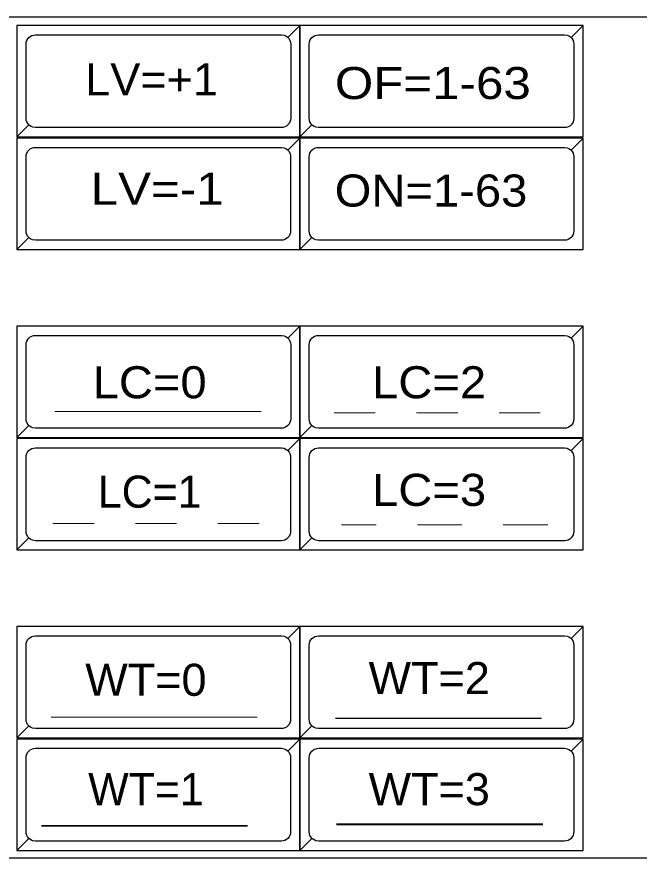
# Model space of a CAD drawing. Extents: x 16898 to 16911.6, y 15837.8 to 15842.
# Drawn here: x 16899.217 to 16900.726, y 15839.972 to 15842.012 of the extents above; entities that cross this region are included whole.
import ezdxf
from ezdxf.enums import TextEntityAlignment as Align

# ---------------------------------------------------------------- set-up
doc = ezdxf.new("R2010")
doc.units = 0
doc.header["$LTSCALE"] = 0.018
for name, pattern in [('DOTTED', [1.5, 0.3, -1.2]), ('LONG_DASHED', [7.5, 6, -1.5]), ('MEDIUM_DASHED', [4.5, 3, -1.5])]:
    doc.linetypes.add(name, pattern=pattern)
for name, color, linetype, lineweight in [('1', 7, 'Continuous', 25), ('2', 7, 'Continuous', 13), ('5', 7, 'Continuous', 13)]:
    doc.layers.add(name, color=color, linetype=linetype, lineweight=lineweight)

msp = doc.modelspace()

# ---------------------------------------------------------------- linework, layer by layer
at = {"layer": '1'}
for points in [[(16897.9955, 15839.9723), (16897.9955, 15842.0124), (16911.4764, 15842.0124), (16911.5674, 15841.9251), (16911.5674, 15840.0599), (16911.4764, 15839.9723)], [(16899.2172, 15841.7212), (16899.9036, 15841.7212), (16899.9036, 15841.9912), (16899.2172, 15841.9912)], [(16899.2172, 15841.7212), (16899.9036, 15841.7212), (16899.9036, 15841.9912), (16899.8745, 15841.9621), (16899.8773, 15841.9587), (16899.8794, 15841.9548), (16899.8806, 15841.9506), (16899.8811, 15841.9462), (16899.8811, 15841.7662), (16899.8806, 15841.7618), (16899.8794, 15841.7576), (16899.8773, 15841.7537), (16899.8745, 15841.7503), (16899.8745, 15841.7503), (16899.8711, 15841.7475), (16899.8672, 15841.7454), (16899.863, 15841.7441), (16899.8586, 15841.7437), (16899.2622, 15841.7437), (16899.2556, 15841.7447), (16899.2516, 15841.7464), (16899.2479, 15841.7488), (16899.2463, 15841.7503)], [(16899.9036, 15841.9912), (16899.2172, 15841.9912), (16899.2172, 15841.7212), (16899.2463, 15841.7503), (16899.2435, 15841.7537), (16899.2414, 15841.7576), (16899.2401, 15841.7618), (16899.2397, 15841.7662), (16899.2397, 15841.9462), (16899.2401, 15841.9506), (16899.2414, 15841.9548), (16899.2435, 15841.9587), (16899.2463, 15841.9621), (16899.2463, 15841.9621), (16899.2497, 15841.9649), (16899.2536, 15841.967), (16899.2578, 15841.9682), (16899.2622, 15841.9687), (16899.8586, 15841.9687), (16899.8652, 15841.9677), (16899.8692, 15841.966), (16899.8729, 15841.9636), (16899.8745, 15841.9621)], [(16899.9036, 15841.7212), (16900.59, 15841.7212), (16900.59, 15841.9912), (16899.9036, 15841.9912)], [(16899.9036, 15841.7212), (16900.59, 15841.7212), (16900.59, 15841.9912), (16900.5609, 15841.9621), (16900.5637, 15841.9587), (16900.5658, 15841.9548), (16900.567, 15841.9506), (16900.5675, 15841.9462), (16900.5675, 15841.7662), (16900.567, 15841.7618), (16900.5658, 15841.7576), (16900.5637, 15841.7537), (16900.5609, 15841.7503), (16900.5609, 15841.7503), (16900.5575, 15841.7475), (16900.5536, 15841.7454), (16900.5494, 15841.7441), (16900.545, 15841.7437), (16899.9486, 15841.7437), (16899.942, 15841.7447), (16899.938, 15841.7464), (16899.9343, 15841.7488), (16899.9327, 15841.7503)], [(16900.59, 15841.9912), (16899.9036, 15841.9912), (16899.9036, 15841.7212), (16899.9327, 15841.7503), (16899.9299, 15841.7537), (16899.9278, 15841.7576), (16899.9265, 15841.7618), (16899.9261, 15841.7662), (16899.9261, 15841.9462), (16899.9265, 15841.9506), (16899.9278, 15841.9548), (16899.9299, 15841.9587), (16899.9327, 15841.9621), (16899.9327, 15841.9621), (16899.9361, 15841.9649), (16899.94, 15841.967), (16899.9442, 15841.9682), (16899.9486, 15841.9687), (16900.545, 15841.9687), (16900.5516, 15841.9677), (16900.5556, 15841.966), (16900.5593, 15841.9636), (16900.5609, 15841.9621)], [(16899.2171, 15841.4483), (16899.9035, 15841.4483), (16899.9035, 15841.7183), (16899.2171, 15841.7183)], [(16899.2171, 15841.4483), (16899.9035, 15841.4483), (16899.9035, 15841.7183), (16899.8744, 15841.6892), (16899.8772, 15841.6858), (16899.8793, 15841.6819), (16899.8805, 15841.6777), (16899.881, 15841.6733), (16899.881, 15841.4933), (16899.8805, 15841.4889), (16899.8793, 15841.4847), (16899.8772, 15841.4808), (16899.8744, 15841.4774), (16899.8744, 15841.4774), (16899.871, 15841.4746), (16899.8671, 15841.4725), (16899.8629, 15841.4712), (16899.8585, 15841.4708), (16899.2621, 15841.4708), (16899.2555, 15841.4718), (16899.2515, 15841.4735), (16899.2478, 15841.4759), (16899.2462, 15841.4774)], [(16899.9035, 15841.7183), (16899.2171, 15841.7183), (16899.2171, 15841.4483), (16899.2462, 15841.4774), (16899.2434, 15841.4808), (16899.2413, 15841.4847), (16899.24, 15841.4889), (16899.2396, 15841.4933), (16899.2396, 15841.6733), (16899.24, 15841.6777), (16899.2413, 15841.6819), (16899.2434, 15841.6858), (16899.2462, 15841.6892), (16899.2462, 15841.6892), (16899.2496, 15841.692), (16899.2535, 15841.6941), (16899.2577, 15841.6953), (16899.2621, 15841.6958), (16899.8585, 15841.6958), (16899.8651, 15841.6948), (16899.8691, 15841.6931), (16899.8728, 15841.6907), (16899.8744, 15841.6892)], [(16899.9036, 15841.4483), (16900.59, 15841.4483), (16900.59, 15841.7183), (16899.9036, 15841.7183)], [(16899.9036, 15841.4483), (16900.59, 15841.4483), (16900.59, 15841.7183), (16900.5609, 15841.6892), (16900.5637, 15841.6858), (16900.5658, 15841.6819), (16900.567, 15841.6777), (16900.5675, 15841.6733), (16900.5675, 15841.4933), (16900.567, 15841.4889), (16900.5658, 15841.4847), (16900.5637, 15841.4808), (16900.5609, 15841.4774), (16900.5609, 15841.4774), (16900.5575, 15841.4746), (16900.5536, 15841.4725), (16900.5494, 15841.4712), (16900.545, 15841.4708), (16899.9486, 15841.4708), (16899.942, 15841.4718), (16899.938, 15841.4735), (16899.9343, 15841.4759), (16899.9327, 15841.4774)], [(16900.59, 15841.7183), (16899.9036, 15841.7183), (16899.9036, 15841.4483), (16899.9327, 15841.4774), (16899.9299, 15841.4808), (16899.9278, 15841.4847), (16899.9265, 15841.4889), (16899.9261, 15841.4933), (16899.9261, 15841.6733), (16899.9265, 15841.6777), (16899.9278, 15841.6819), (16899.9299, 15841.6858), (16899.9327, 15841.6892), (16899.9327, 15841.6892), (16899.9361, 15841.692), (16899.94, 15841.6941), (16899.9442, 15841.6953), (16899.9486, 15841.6958), (16900.545, 15841.6958), (16900.5516, 15841.6948), (16900.5556, 15841.6931), (16900.5593, 15841.6907), (16900.5609, 15841.6892)], [(16899.2172, 15840.9924), (16899.9036, 15840.9924), (16899.9036, 15841.2624), (16899.2172, 15841.2624)], [(16899.2172, 15840.9924), (16899.9036, 15840.9924), (16899.9036, 15841.2624), (16899.8745, 15841.2333), (16899.8773, 15841.2299), (16899.8794, 15841.226), (16899.8806, 15841.2218), (16899.8811, 15841.2174), (16899.8811, 15841.0374), (16899.8806, 15841.033), (16899.8794, 15841.0288), (16899.8773, 15841.0249), (16899.8745, 15841.0215), (16899.8745, 15841.0215), (16899.8711, 15841.0187), (16899.8672, 15841.0166), (16899.863, 15841.0153), (16899.8586, 15841.0149), (16899.2622, 15841.0149), (16899.2556, 15841.0159), (16899.2516, 15841.0176), (16899.2479, 15841.02), (16899.2463, 15841.0215)], [(16899.9036, 15841.2624), (16899.2172, 15841.2624), (16899.2172, 15840.9924), (16899.2463, 15841.0215), (16899.2435, 15841.0249), (16899.2414, 15841.0288), (16899.2401, 15841.033), (16899.2397, 15841.0374), (16899.2397, 15841.2174), (16899.2401, 15841.2218), (16899.2414, 15841.226), (16899.2435, 15841.2299), (16899.2463, 15841.2333), (16899.2463, 15841.2333), (16899.2497, 15841.2361), (16899.2536, 15841.2382), (16899.2578, 15841.2394), (16899.2622, 15841.2399), (16899.8586, 15841.2399), (16899.8652, 15841.2389), (16899.8692, 15841.2372), (16899.8729, 15841.2348), (16899.8745, 15841.2333)], [(16899.9036, 15840.9924), (16900.59, 15840.9924), (16900.59, 15841.2624), (16899.9036, 15841.2624)], [(16899.9036, 15840.9924), (16900.59, 15840.9924), (16900.59, 15841.2624), (16900.5609, 15841.2333), (16900.5637, 15841.2299), (16900.5658, 15841.226), (16900.567, 15841.2218), (16900.5675, 15841.2174), (16900.5675, 15841.0374), (16900.567, 15841.033), (16900.5658, 15841.0288), (16900.5637, 15841.0249), (16900.5609, 15841.0215), (16900.5609, 15841.0215), (16900.5575, 15841.0187), (16900.5536, 15841.0166), (16900.5494, 15841.0153), (16900.545, 15841.0149), (16899.9486, 15841.0149), (16899.942, 15841.0159), (16899.938, 15841.0176), (16899.9343, 15841.02), (16899.9327, 15841.0215)], [(16900.59, 15841.2624), (16899.9036, 15841.2624), (16899.9036, 15840.9924), (16899.9327, 15841.0215), (16899.9299, 15841.0249), (16899.9278, 15841.0288), (16899.9265, 15841.033), (16899.9261, 15841.0374), (16899.9261, 15841.2174), (16899.9265, 15841.2218), (16899.9278, 15841.226), (16899.9299, 15841.2299), (16899.9327, 15841.2333), (16899.9327, 15841.2333), (16899.9361, 15841.2361), (16899.94, 15841.2382), (16899.9442, 15841.2394), (16899.9486, 15841.2399), (16900.545, 15841.2399), (16900.5516, 15841.2389), (16900.5556, 15841.2372), (16900.5593, 15841.2348), (16900.5609, 15841.2333)], [(16899.2171, 15840.7196), (16899.9035, 15840.7196), (16899.9035, 15840.9896), (16899.2171, 15840.9896)], [(16899.2171, 15840.7196), (16899.9035, 15840.7196), (16899.9035, 15840.9896), (16899.8744, 15840.9605), (16899.8772, 15840.9571), (16899.8793, 15840.9532), (16899.8805, 15840.949), (16899.881, 15840.9446), (16899.881, 15840.7646), (16899.8805, 15840.7602), (16899.8793, 15840.756), (16899.8772, 15840.7521), (16899.8744, 15840.7487), (16899.8744, 15840.7487), (16899.871, 15840.7459), (16899.8671, 15840.7438), (16899.8629, 15840.7425), (16899.8585, 15840.7421), (16899.2621, 15840.7421), (16899.2555, 15840.7431), (16899.2515, 15840.7448), (16899.2478, 15840.7472), (16899.2462, 15840.7487)], [(16899.9035, 15840.9896), (16899.2171, 15840.9896), (16899.2171, 15840.7196), (16899.2462, 15840.7487), (16899.2434, 15840.7521), (16899.2413, 15840.756), (16899.24, 15840.7602), (16899.2396, 15840.7646), (16899.2396, 15840.9446), (16899.24, 15840.949), (16899.2413, 15840.9532), (16899.2434, 15840.9571), (16899.2462, 15840.9605), (16899.2462, 15840.9605), (16899.2496, 15840.9633), (16899.2535, 15840.9654), (16899.2577, 15840.9666), (16899.2621, 15840.9671), (16899.8585, 15840.9671), (16899.8651, 15840.9661), (16899.8691, 15840.9644), (16899.8728, 15840.962), (16899.8744, 15840.9605)], [(16899.9036, 15840.7196), (16900.59, 15840.7196), (16900.59, 15840.9896), (16899.9036, 15840.9896)], [(16899.9036, 15840.7196), (16900.59, 15840.7196), (16900.59, 15840.9896), (16900.5609, 15840.9605), (16900.5637, 15840.9571), (16900.5658, 15840.9532), (16900.567, 15840.949), (16900.5675, 15840.9446), (16900.5675, 15840.7646), (16900.567, 15840.7602), (16900.5658, 15840.756), (16900.5637, 15840.7521), (16900.5609, 15840.7487), (16900.5609, 15840.7487), (16900.5575, 15840.7459), (16900.5536, 15840.7438), (16900.5494, 15840.7425), (16900.545, 15840.7421), (16899.9486, 15840.7421), (16899.942, 15840.7431), (16899.938, 15840.7448), (16899.9343, 15840.7472), (16899.9327, 15840.7487)], [(16900.59, 15840.9896), (16899.9036, 15840.9896), (16899.9036, 15840.7196), (16899.9327, 15840.7487), (16899.9299, 15840.7521), (16899.9278, 15840.756), (16899.9265, 15840.7602), (16899.9261, 15840.7646), (16899.9261, 15840.9446), (16899.9265, 15840.949), (16899.9278, 15840.9532), (16899.9299, 15840.9571), (16899.9327, 15840.9605), (16899.9327, 15840.9605), (16899.9361, 15840.9633), (16899.94, 15840.9654), (16899.9442, 15840.9666), (16899.9486, 15840.9671), (16900.545, 15840.9671), (16900.5516, 15840.9661), (16900.5556, 15840.9644), (16900.5593, 15840.962), (16900.5609, 15840.9605)], [(16899.2171, 15840.264), (16899.9035, 15840.264), (16899.9035, 15840.534), (16899.2171, 15840.534)], [(16899.2171, 15840.264), (16899.9035, 15840.264), (16899.9035, 15840.534), (16899.8744, 15840.5049), (16899.8772, 15840.5015), (16899.8793, 15840.4976), (16899.8805, 15840.4934), (16899.881, 15840.489), (16899.881, 15840.309), (16899.8805, 15840.3046), (16899.8793, 15840.3004), (16899.8772, 15840.2965), (16899.8744, 15840.2931), (16899.8744, 15840.2931), (16899.871, 15840.2903), (16899.8671, 15840.2882), (16899.8629, 15840.2869), (16899.8585, 15840.2865), (16899.2621, 15840.2865), (16899.2555, 15840.2875), (16899.2515, 15840.2892), (16899.2478, 15840.2916), (16899.2462, 15840.2931)], [(16899.9035, 15840.534), (16899.2171, 15840.534), (16899.2171, 15840.264), (16899.2462, 15840.2931), (16899.2434, 15840.2965), (16899.2413, 15840.3004), (16899.24, 15840.3046), (16899.2396, 15840.309), (16899.2396, 15840.489), (16899.24, 15840.4934), (16899.2413, 15840.4976), (16899.2434, 15840.5015), (16899.2462, 15840.5049), (16899.2462, 15840.5049), (16899.2496, 15840.5077), (16899.2535, 15840.5098), (16899.2577, 15840.511), (16899.2621, 15840.5115), (16899.8585, 15840.5115), (16899.8651, 15840.5105), (16899.8691, 15840.5088), (16899.8728, 15840.5064), (16899.8744, 15840.5049)], [(16899.9036, 15840.264), (16900.59, 15840.264), (16900.59, 15840.534), (16899.9036, 15840.534)], [(16899.9036, 15840.264), (16900.59, 15840.264), (16900.59, 15840.534), (16900.5609, 15840.5049), (16900.5637, 15840.5015), (16900.5658, 15840.4976), (16900.567, 15840.4934), (16900.5675, 15840.489), (16900.5675, 15840.309), (16900.567, 15840.3046), (16900.5658, 15840.3004), (16900.5637, 15840.2965), (16900.5609, 15840.2931), (16900.5609, 15840.2931), (16900.5575, 15840.2903), (16900.5536, 15840.2882), (16900.5494, 15840.2869), (16900.545, 15840.2865), (16899.9486, 15840.2865), (16899.942, 15840.2875), (16899.938, 15840.2892), (16899.9343, 15840.2916), (16899.9327, 15840.2931)], [(16900.59, 15840.534), (16899.9036, 15840.534), (16899.9036, 15840.264), (16899.9327, 15840.2931), (16899.9299, 15840.2965), (16899.9278, 15840.3004), (16899.9265, 15840.3046), (16899.9261, 15840.309), (16899.9261, 15840.489), (16899.9265, 15840.4934), (16899.9278, 15840.4976), (16899.9299, 15840.5015), (16899.9327, 15840.5049), (16899.9327, 15840.5049), (16899.9361, 15840.5077), (16899.94, 15840.5098), (16899.9442, 15840.511), (16899.9486, 15840.5115), (16900.545, 15840.5115), (16900.5516, 15840.5105), (16900.5556, 15840.5088), (16900.5593, 15840.5064), (16900.5609, 15840.5049)], [(16899.2171, 15839.9912), (16899.9035, 15839.9912), (16899.9035, 15840.2612), (16899.2171, 15840.2612)], [(16899.2171, 15839.9912), (16899.9035, 15839.9912), (16899.9035, 15840.2612), (16899.8744, 15840.2321), (16899.8772, 15840.2287), (16899.8793, 15840.2248), (16899.8805, 15840.2206), (16899.881, 15840.2162), (16899.881, 15840.0362), (16899.8805, 15840.0318), (16899.8793, 15840.0276), (16899.8772, 15840.0237), (16899.8744, 15840.0203), (16899.8744, 15840.0203), (16899.871, 15840.0175), (16899.8671, 15840.0154), (16899.8629, 15840.0141), (16899.8585, 15840.0137), (16899.2621, 15840.0137), (16899.2555, 15840.0147), (16899.2515, 15840.0164), (16899.2478, 15840.0188), (16899.2462, 15840.0203)], [(16899.9035, 15840.2612), (16899.2171, 15840.2612), (16899.2171, 15839.9912), (16899.2462, 15840.0203), (16899.2434, 15840.0237), (16899.2413, 15840.0276), (16899.24, 15840.0318), (16899.2396, 15840.0362), (16899.2396, 15840.2162), (16899.24, 15840.2206), (16899.2413, 15840.2248), (16899.2434, 15840.2287), (16899.2462, 15840.2321), (16899.2462, 15840.2321), (16899.2496, 15840.2349), (16899.2535, 15840.237), (16899.2577, 15840.2382), (16899.2621, 15840.2387), (16899.8585, 15840.2387), (16899.8651, 15840.2377), (16899.8691, 15840.236), (16899.8728, 15840.2336), (16899.8744, 15840.2321)], [(16899.9036, 15839.9912), (16900.59, 15839.9912), (16900.59, 15840.2612), (16899.9036, 15840.2612)], [(16899.9036, 15839.9912), (16900.59, 15839.9912), (16900.59, 15840.2612), (16900.5609, 15840.2321), (16900.5637, 15840.2287), (16900.5658, 15840.2248), (16900.567, 15840.2206), (16900.5675, 15840.2162), (16900.5675, 15840.0362), (16900.567, 15840.0318), (16900.5658, 15840.0276), (16900.5637, 15840.0237), (16900.5609, 15840.0203), (16900.5609, 15840.0203), (16900.5575, 15840.0175), (16900.5536, 15840.0154), (16900.5494, 15840.0141), (16900.545, 15840.0137), (16899.9486, 15840.0137), (16899.942, 15840.0147), (16899.938, 15840.0164), (16899.9343, 15840.0188), (16899.9327, 15840.0203)], [(16900.59, 15840.2612), (16899.9036, 15840.2612), (16899.9036, 15839.9912), (16899.9327, 15840.0203), (16899.9299, 15840.0237), (16899.9278, 15840.0276), (16899.9265, 15840.0318), (16899.9261, 15840.0362), (16899.9261, 15840.2162), (16899.9265, 15840.2206), (16899.9278, 15840.2248), (16899.9299, 15840.2287), (16899.9327, 15840.2321), (16899.9327, 15840.2321), (16899.9361, 15840.2349), (16899.94, 15840.237), (16899.9442, 15840.2382), (16899.9486, 15840.2387), (16900.545, 15840.2387), (16900.5516, 15840.2377), (16900.5556, 15840.236), (16900.5593, 15840.2336), (16900.5609, 15840.2321)]]:
    msp.add_lwpolyline(points, close=True, dxfattribs=at)
at = {"layer": '2'}
msp.add_lwpolyline([(16897.9955, 15839.9723), (16897.9955, 15842.0124), (16911.4764, 15842.0124), (16911.5674, 15841.9251), (16911.5674, 15840.0599), (16911.4764, 15839.9723)], close=True, dxfattribs=at)
at = {"layer": '5'}
for p, q in [((16899.8093, 15841.0554), (16899.3096, 15841.0554)), ((16899.8, 15840.3143), (16899.3004, 15840.3143))]:
    msp.add_line(p, q, dxfattribs=at)
at = {"layer": '5', "linetype": 'DOTTED'}
msp.add_line((16900.4862, 15841.0525), (16899.9865, 15841.0525), dxfattribs=at)
at = {"layer": '5', "linetype": 'MEDIUM_DASHED'}
msp.add_line((16899.8045, 15840.7836), (16899.3048, 15840.7836), dxfattribs=at)
at = {"layer": '5', "linetype": 'LONG_DASHED'}
msp.add_line((16900.5042, 15840.7806), (16900.0045, 15840.7806), dxfattribs=at)
at = {"layer": '5', "lineweight": 25}
msp.add_line((16900.4891, 15840.3113), (16899.9894, 15840.3113), dxfattribs=at)
at = {"layer": '5', "lineweight": 35}
msp.add_line((16899.7764, 15840.051), (16899.2767, 15840.051), dxfattribs=at)
at = {"layer": '5', "lineweight": 40}
msp.add_line((16900.4921, 15840.054), (16899.9925, 15840.054), dxfattribs=at)

# ---------------------------------------------------------------- texts
at = {"layer": '5'}
for s, width, p in [('LV=+1', 1.05, (16899.5439, 15841.8217)), ('LV=+1', 1.05, (16899.5439, 15841.8217)), ('OF=1-63', 1.15, (16900.2258, 15841.813)), ('LV=-1', 1.15, (16899.5574, 15841.5567)), ('ON=1-63', 1.1, (16900.2213, 15841.5523)), ('LC=0', 1.1, (16899.5392, 15841.0874)), ('LC=2', 1.1, (16900.2167, 15841.0874)), ('LC=3', 1.1, (16900.2167, 15840.8265)), ('WT=0', 1.05, (16899.5301, 15840.366)), ('WT=2', 1.05, (16900.217, 15840.3702)), ('WT=3', 1.05, (16900.217, 15840.1008))]:
    msp.add_text(s, height=0.07772, dxfattribs=dict(at, width=width)).set_placement(p, align=Align.CENTER)
for s, p in [('LC=1', (16899.5393, 15840.8222)), ('WT=1', (16899.5302, 15840.1008))]:
    msp.add_text(s, height=0.07772, dxfattribs=at).set_placement(p, align=Align.CENTER)

doc.saveas('drawing.dxf')
